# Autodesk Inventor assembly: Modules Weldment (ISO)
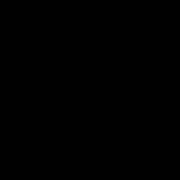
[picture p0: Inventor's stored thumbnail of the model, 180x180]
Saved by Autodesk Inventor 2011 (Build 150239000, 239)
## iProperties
Created: 2007-02
Part Number: Modules Weldment (ISO)
Document SubType Name: Weldment
Designer: Wally Jones
Weld Material: Welded Aluminum-6061
Author: Wally Jones
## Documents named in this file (1)
- C:\CAD Courses 1\Inventor\Templates\Metric\Modules Weldment (ISO).iam
